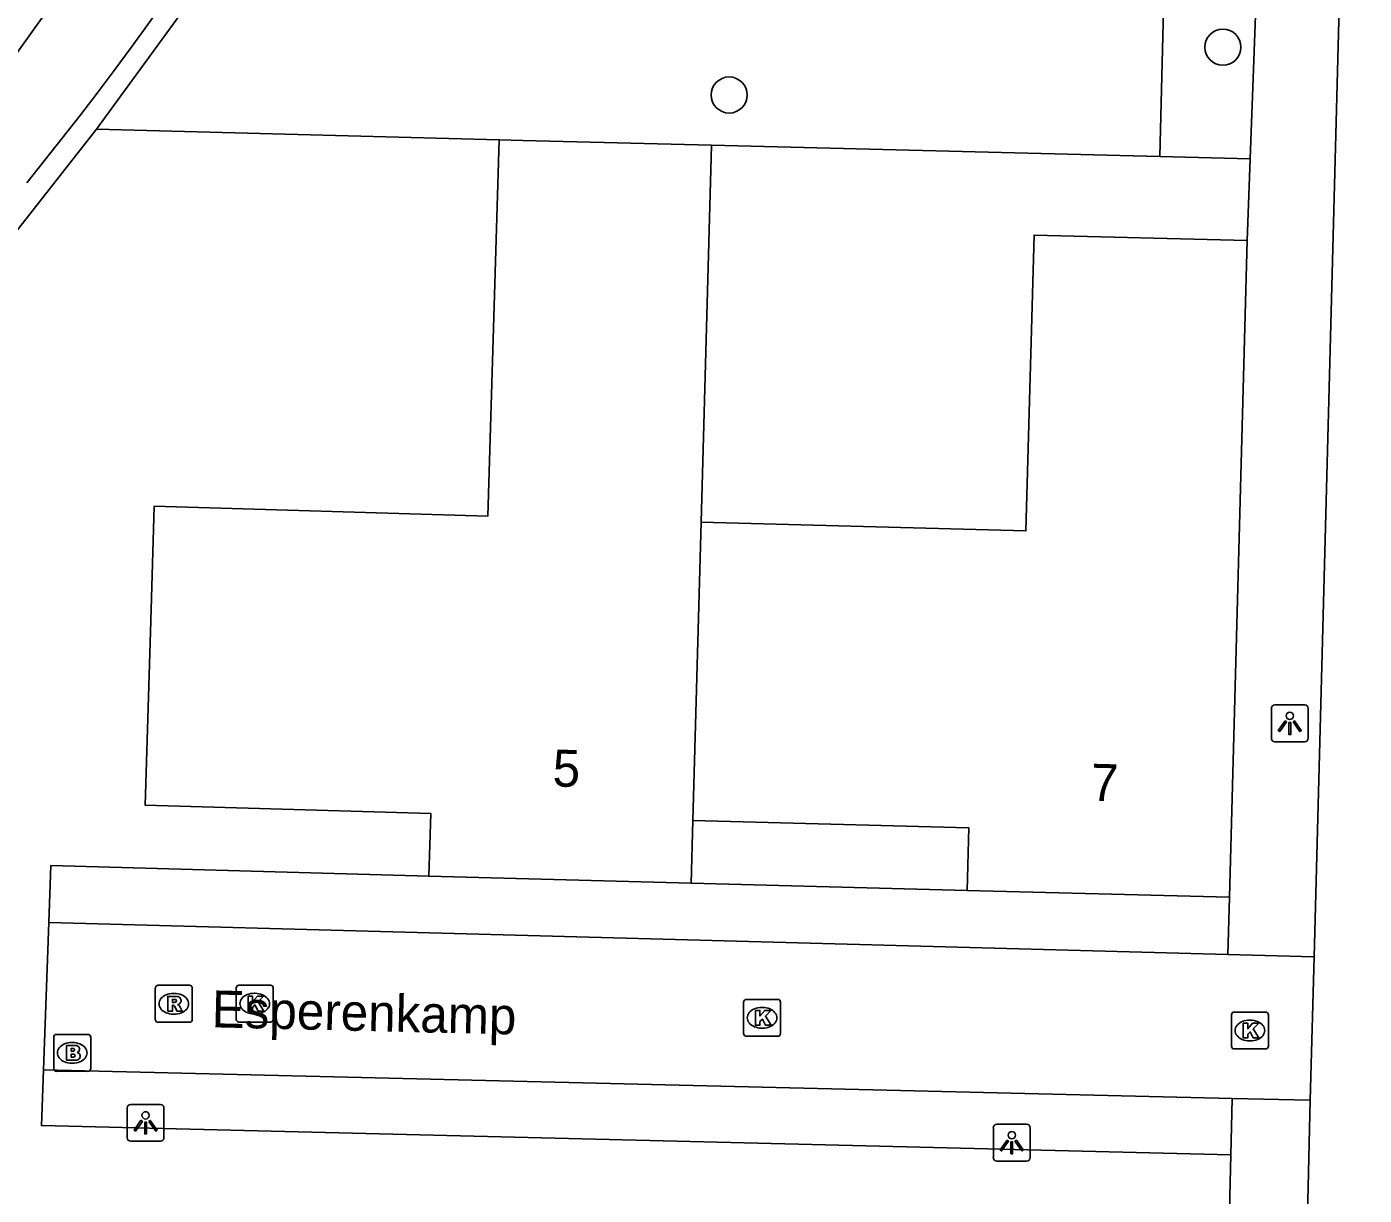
# Model space of a CAD drawing. Extents: x 162082 to 163393, y 388091 to 388632.
# Drawn here: x 162233.21 to 162269.43, y 388303.46 to 388335.1 of the extents above; entities that cross this region are included whole.
import ezdxf

# ---------------------------------------------------------------- set-up
doc = ezdxf.new("R2010")
doc.units = 0
for name, color, linetype in [('IMGEO_Boom', 7, 'Continuous'), ('IMGEO_Brandkraan', 7, 'Continuous'), ('IMGEO_Fietspad_gesloten', 7, 'Continuous'), ('IMGEO_Groenvoorziening', 7, 'Continuous'), ('IMGEO_Kolk', 7, 'Continuous'), ('IMGEO_Lichtpunt', 7, 'Continuous'), ('IMGEO_Muur', 7, 'Continuous'), ('IMGEO_Openbare_ruimte_label', 7, 'Continuous'), ('IMGEO_Pand', 7, 'Continuous'), ('IMGEO_Pand_nummerreeks', 7, 'Continuous'), ('IMGEO_Rijbaan_lokaal_open', 7, 'Continuous'), ('IMGEO_Rioolput', 7, 'Continuous'), ('IMGEO_Voetpad_open', 7, 'Continuous')]:
    doc.layers.add(name, color=color, linetype=linetype)

msp = doc.modelspace()

# ---------------------------------------------------------------- linework, layer by layer
at = {"layer": 'IMGEO_Boom'}
for centre in [(162265.604, 388334.549), (162252.23, 388333.255)]:
    msp.add_circle(centre, 0.489, dxfattribs=at)
at = {"layer": 'IMGEO_Brandkraan'}
for p, q in [((162234.015, 388307.815), (162234.867, 388307.815)), ((162233.94, 388306.889), (162233.94, 388307.741)), ((162234.428, 388307.595), (162234.453, 388307.595)), ((162234.941, 388307.741), (162234.941, 388306.889)), ((162234.867, 388306.815), (162234.015, 388306.815)), ((162234.451, 388307.035), (162234.426, 388307.035))]:
    msp.add_line(p, q, dxfattribs=at)
for points in [[(162234.015, 388307.815), (162234.867, 388307.815)], [(162233.94, 388306.889), (162233.94, 388307.741)], [(162234.288, 388307.515), (162234.288, 388307.115), (162234.501, 388307.115)], [(162234.519, 388307.515), (162234.288, 388307.515)], [(162234.941, 388307.741), (162234.941, 388306.889)], [(162234.467, 388307.434), (162234.413, 388307.434), (162234.413, 388307.358)], [(162234.413, 388307.358), (162234.466, 388307.358)], [(162234.475, 388307.282), (162234.413, 388307.282), (162234.413, 388307.201)], [(162234.413, 388307.201), (162234.475, 388307.201)], [(162234.867, 388306.815), (162234.015, 388306.815)]]:
    msp.add_lwpolyline(points, dxfattribs=at)
for centre, radius, start, end in [((162234.017, 388307.739), 0.0765, 91.552, 178.448), ((162234.017, 388307.739), 0.0765, 91.552, 178.448), ((162234.865, 388307.739), 0.0765, 1.552, 88.448), ((162234.865, 388307.739), 0.0765, 1.552, 88.448), ((162234.523, 388307.37), 0.145, 59.4692, 91.5367), ((162234.548, 388307.417), 0.0922, 285.5137, 58.1501), ((162234.468, 388307.396), 0.0379, 267.8285, 90.9355), ((162234.476, 388307.241), 0.0404, 269.8759, 90.5077), ((162234.507, 388307.366), 0.251, 268.6676, 293.5347), ((162234.553, 388307.225), 0.105, 301.3115, 78.989), ((162234.017, 388306.891), 0.0765, 181.552, 268.448), ((162234.017, 388306.891), 0.0765, 181.552, 268.448), ((162234.865, 388306.891), 0.0765, 271.552, 358.448), ((162234.865, 388306.891), 0.0765, 271.552, 358.448)]:
    msp.add_arc(centre, radius, start, end, dxfattribs=at)
for centre, major_axis, ratio, start_param, end_param in [((162234.427, 388307.315), (-0.387, 0.002), 0.722429, 4.712389, 7.853982), ((162234.452, 388307.315), (-0.39, 0.002), 0.717154, 1.570796, 4.712389)]:
    msp.add_ellipse(centre, major_axis=major_axis, ratio=ratio, start_param=start_param, end_param=end_param, dxfattribs=at)
at = {"layer": 'IMGEO_Fietspad_gesloten'}
msp.add_lwpolyline([(162231.513, 388332.41), (162235.411, 388337.857), (162240.451, 388345.768), (162241.498, 388347.847)], dxfattribs=at)
at = {"layer": 'IMGEO_Groenvoorziening'}
for points in [[(162263.899, 388331.585), (162264.185, 388343.163)], [(162246, 388332.04), (162235.098, 388332.325)], [(162251.75, 388331.897), (162263.899, 388331.585)], [(162263.899, 388331.585), (162266.342, 388331.522)]]:
    msp.add_lwpolyline(points, dxfattribs=at)
at = {"layer": 'IMGEO_Kolk'}
for p, q in [((162238.882, 388308.222), (162238.882, 388309.074)), ((162238.957, 388309.148), (162239.809, 388309.148)), ((162239.37, 388308.928), (162239.395, 388308.928)), ((162239.883, 388309.074), (162239.883, 388308.222)), ((162252.622, 388307.838), (162252.622, 388308.69)), ((162252.697, 388308.764), (162253.549, 388308.764)), ((162253.11, 388308.544), (162253.135, 388308.544)), ((162253.623, 388308.69), (162253.623, 388307.838)), ((162239.393, 388308.368), (162239.368, 388308.368)), ((162265.834, 388307.494), (162265.834, 388308.346)), ((162265.909, 388308.42), (162266.761, 388308.42)), ((162266.322, 388308.2), (162266.347, 388308.2)), ((162266.835, 388308.346), (162266.835, 388307.494)), ((162239.809, 388308.148), (162238.957, 388308.148)), ((162253.133, 388307.984), (162253.108, 388307.984)), ((162253.549, 388307.764), (162252.697, 388307.764)), ((162266.345, 388307.64), (162266.32, 388307.64)), ((162266.761, 388307.42), (162265.909, 388307.42))]:
    msp.add_line(p, q, dxfattribs=at)
for points in [[(162238.882, 388308.222), (162238.882, 388309.074)], [(162238.957, 388309.148), (162239.809, 388309.148)], [(162239.883, 388309.074), (162239.883, 388308.222)], [(162239.203, 388308.848), (162239.326, 388308.848), (162239.326, 388308.697), (162239.456, 388308.848), (162239.62, 388308.848), (162239.474, 388308.697), (162239.627, 388308.448), (162239.475, 388308.448), (162239.39, 388308.612), (162239.326, 388308.545), (162239.326, 388308.448), (162239.203, 388308.448), (162239.203, 388308.848)], [(162252.622, 388307.838), (162252.622, 388308.69)], [(162252.697, 388308.764), (162253.549, 388308.764)], [(162253.623, 388308.69), (162253.623, 388307.838)], [(162252.943, 388308.464), (162253.066, 388308.464), (162253.066, 388308.313), (162253.196, 388308.464), (162253.36, 388308.464), (162253.214, 388308.313), (162253.367, 388308.064), (162253.215, 388308.064), (162253.13, 388308.228), (162253.066, 388308.161), (162253.066, 388308.064), (162252.943, 388308.064), (162252.943, 388308.464)], [(162265.834, 388307.494), (162265.834, 388308.346)], [(162265.909, 388308.42), (162266.761, 388308.42)], [(162266.835, 388308.346), (162266.835, 388307.494)], [(162239.809, 388308.148), (162238.957, 388308.148)], [(162266.155, 388308.12), (162266.278, 388308.12), (162266.278, 388307.969), (162266.408, 388308.12), (162266.572, 388308.12), (162266.426, 388307.969), (162266.579, 388307.72), (162266.427, 388307.72), (162266.342, 388307.884), (162266.278, 388307.817), (162266.278, 388307.72), (162266.155, 388307.72), (162266.155, 388308.12)], [(162253.549, 388307.764), (162252.697, 388307.764)], [(162266.761, 388307.42), (162265.909, 388307.42)]]:
    msp.add_lwpolyline(points, dxfattribs=at)
for centre, start, end in [((162238.959, 388309.072), 91.552, 178.448), ((162238.959, 388309.072), 91.552, 178.448), ((162239.807, 388309.072), 1.552, 88.448), ((162239.807, 388309.072), 1.552, 88.448), ((162252.699, 388308.688), 91.552, 178.448), ((162252.699, 388308.688), 91.552, 178.448), ((162253.547, 388308.688), 1.552, 88.448), ((162253.547, 388308.688), 1.552, 88.448), ((162238.959, 388308.224), 181.552, 268.448), ((162238.959, 388308.224), 181.552, 268.448), ((162239.807, 388308.224), 271.552, 358.448), ((162239.807, 388308.224), 271.552, 358.448), ((162265.911, 388308.344), 91.552, 178.448), ((162265.911, 388308.344), 91.552, 178.448), ((162266.759, 388308.344), 1.552, 88.448), ((162266.759, 388308.344), 1.552, 88.448), ((162252.699, 388307.84), 181.552, 268.448), ((162252.699, 388307.84), 181.552, 268.448), ((162253.547, 388307.84), 271.552, 358.448), ((162253.547, 388307.84), 271.552, 358.448), ((162265.911, 388307.496), 181.552, 268.448), ((162265.911, 388307.496), 181.552, 268.448), ((162266.759, 388307.496), 271.552, 358.448), ((162266.759, 388307.496), 271.552, 358.448)]:
    msp.add_arc(centre, 0.0765, start, end, dxfattribs=at)
for centre, major_axis, ratio, start_param, end_param in [((162239.369, 388308.648), (-0.387, 0.002), 0.722429, 4.712389, 7.853982), ((162239.394, 388308.648), (-0.39, 0.002), 0.717154, 1.570796, 4.712389), ((162253.109, 388308.264), (-0.387, 0.002), 0.722429, 4.712389, 7.853982), ((162253.134, 388308.264), (-0.39, 0.002), 0.717154, 1.570796, 4.712389), ((162266.321, 388307.92), (-0.387, 0.002), 0.722429, 4.712389, 7.853982), ((162266.346, 388307.92), (-0.39, 0.002), 0.717154, 1.570796, 4.712389)]:
    msp.add_ellipse(centre, major_axis=major_axis, ratio=ratio, start_param=start_param, end_param=end_param, dxfattribs=at)
at = {"layer": 'IMGEO_Lichtpunt'}
for p, q in [((162266.916, 388316.642), (162266.916, 388315.835)), ((162266.916, 388316.642), (162266.916, 388315.835)), ((162267.818, 388316.737), (162267.01, 388316.737)), ((162267.818, 388316.737), (162267.01, 388316.737)), ((162267.912, 388315.835), (162267.912, 388316.642)), ((162267.912, 388315.835), (162267.912, 388316.642)), ((162267.01, 388315.741), (162267.818, 388315.741)), ((162267.01, 388315.741), (162267.818, 388315.741)), ((162235.929, 388305.824), (162235.929, 388305.017)), ((162235.929, 388305.824), (162235.929, 388305.017)), ((162236.831, 388305.919), (162236.023, 388305.919)), ((162236.831, 388305.919), (162236.023, 388305.919)), ((162236.925, 388305.017), (162236.925, 388305.824)), ((162236.925, 388305.017), (162236.925, 388305.824)), ((162259.386, 388305.287), (162259.386, 388304.48)), ((162259.386, 388305.287), (162259.386, 388304.48)), ((162260.288, 388305.382), (162259.48, 388305.382)), ((162260.288, 388305.382), (162259.48, 388305.382)), ((162260.382, 388304.48), (162260.382, 388305.287)), ((162260.382, 388304.48), (162260.382, 388305.287)), ((162236.023, 388304.923), (162236.831, 388304.923)), ((162236.023, 388304.923), (162236.831, 388304.923)), ((162259.48, 388304.386), (162260.288, 388304.386)), ((162259.48, 388304.386), (162260.288, 388304.386))]:
    msp.add_line(p, q, dxfattribs=at)
for points in [[(162267.29, 388316.306), (162267.329, 388316.278), (162267.141, 388316.016), (162267.103, 388316.043), (162267.29, 388316.306)], [(162267.392, 388316.258), (162267.439, 388316.258), (162267.439, 388315.936), (162267.392, 388315.936), (162267.392, 388316.258)], [(162267.502, 388316.278), (162267.54, 388316.305), (162267.727, 388316.043), (162267.688, 388316.015), (162267.502, 388316.278)], [(162236.303, 388305.488), (162236.342, 388305.46), (162236.154, 388305.198), (162236.116, 388305.225), (162236.303, 388305.488)], [(162236.405, 388305.44), (162236.452, 388305.44), (162236.452, 388305.118), (162236.405, 388305.118), (162236.405, 388305.44)], [(162236.515, 388305.46), (162236.553, 388305.487), (162236.74, 388305.225), (162236.701, 388305.197), (162236.515, 388305.46)], [(162259.76, 388304.951), (162259.799, 388304.923), (162259.611, 388304.661), (162259.573, 388304.688), (162259.76, 388304.951)], [(162259.972, 388304.923), (162260.01, 388304.95), (162260.197, 388304.688), (162260.158, 388304.66), (162259.972, 388304.923)], [(162259.862, 388304.903), (162259.909, 388304.903), (162259.909, 388304.581), (162259.862, 388304.581), (162259.862, 388304.903)]]:
    msp.add_lwpolyline(points, dxfattribs=at)
for centre in [(162267.415, 388316.44), (162236.428, 388305.622), (162259.885, 388305.085)]:
    msp.add_circle(centre, 0.0994, dxfattribs=at)
for centre, start, end in [((162267.01, 388316.642), 90, 180), ((162267.01, 388316.642), 90, 180), ((162267.818, 388316.642), 0, 90), ((162267.818, 388316.642), 0, 90), ((162267.01, 388315.835), 180, 270), ((162267.01, 388315.835), 180, 270), ((162267.818, 388315.835), 270, 0), ((162267.818, 388315.835), 270, 360), ((162236.023, 388305.824), 90, 180), ((162236.023, 388305.824), 90, 180), ((162236.831, 388305.824), 0, 90), ((162236.831, 388305.824), 0, 90), ((162259.48, 388305.287), 90, 180), ((162259.48, 388305.287), 90, 180), ((162260.288, 388305.287), 0, 90), ((162260.288, 388305.287), 0, 90), ((162236.023, 388305.017), 180, 270), ((162236.023, 388305.017), 180, 270), ((162236.831, 388305.017), 270, 0), ((162236.831, 388305.017), 270, 360), ((162259.48, 388304.48), 180, 270), ((162259.48, 388304.48), 180, 270), ((162260.288, 388304.48), 270, 0), ((162260.288, 388304.48), 270, 360)]:
    msp.add_arc(centre, 0.0946, start, end, dxfattribs=at)
at = {"layer": 'IMGEO_Muur'}
for points in [[(162235.098, 388332.325), (162238.245, 388336.654), (162241.627, 388341.988), (162243.888, 388346.035)], [(162235.098, 388332.325), (162227.2, 388322.27)]]:
    msp.add_lwpolyline(points, dxfattribs=at)
msp.add_arc((162161.675, 388388.966), 92.147, 320.92318, 351.45801, dxfattribs=at)
at = {"layer": 'IMGEO_Pand'}
for points in [[(162244.1, 388312.1), (162244.15, 388313.8), (162236.42, 388314.02), (162236.568, 388319.018), (162236.66, 388322.12), (162245.7, 388321.85), (162246, 388332.04)], [(162251.75, 388331.897), (162246.642, 388332.024), (162246, 388332.04)], [(162251.47, 388321.69), (162251.75, 388331.897)], [(162266.26, 388329.31), (162260.49, 388329.46), (162260.27, 388321.45), (162251.47, 388321.69)], [(162265.78, 388311.53), (162266.26, 388329.31)], [(162251.47, 388321.69), (162251.25, 388313.61)], [(162251.2, 388311.91), (162251.25, 388313.61)], [(162251.25, 388313.61), (162258.72, 388313.41), (162258.68, 388311.71)], [(162244.1, 388312.1), (162251.2, 388311.91)], [(162258.68, 388311.71), (162265.78, 388311.53)]]:
    msp.add_lwpolyline(points, dxfattribs=at)
at = {"layer": 'IMGEO_Rijbaan_lokaal_open'}
for points in [[(162267.313, 388361.316), (162269.431, 388361.317), (162268.074, 388309.912)], [(162233.661, 388306.857), (162233.803, 388310.843)], [(162233.803, 388310.843), (162265.741, 388309.975)], [(162265.741, 388309.975), (162268.074, 388309.912)], [(162268.074, 388309.912), (162267.97, 388306.031)], [(162265.854, 388306.082), (162233.661, 388306.857)], [(162267.97, 388306.031), (162265.854, 388306.082)], [(162267.474, 388284.544), (162267.97, 388306.031)]]:
    msp.add_lwpolyline(points, dxfattribs=at)
at = {"layer": 'IMGEO_Rioolput'}
for p, q in [((162236.691, 388308.218), (162236.691, 388309.07)), ((162236.766, 388309.144), (162237.618, 388309.144)), ((162237.179, 388308.924), (162237.204, 388308.924)), ((162237.692, 388309.07), (162237.692, 388308.218)), ((162237.202, 388308.364), (162237.177, 388308.364)), ((162237.618, 388308.144), (162236.766, 388308.144))]:
    msp.add_line(p, q, dxfattribs=at)
for points in [[(162236.691, 388308.218), (162236.691, 388309.07)], [(162236.766, 388309.144), (162237.618, 388309.144)], [(162237.692, 388309.07), (162237.692, 388308.218)], [(162237.28, 388308.842), (162237.028, 388308.844), (162237.028, 388308.444)], [(162237.028, 388308.444), (162237.152, 388308.444), (162237.152, 388308.606), (162237.163, 388308.606)], [(162237.206, 388308.763), (162237.152, 388308.763), (162237.152, 388308.682)], [(162237.152, 388308.682), (162237.204, 388308.682)], [(162237.21, 388308.577), (162237.281, 388308.444), (162237.421, 388308.444), (162237.356, 388308.57)], [(162237.618, 388308.144), (162236.766, 388308.144)]]:
    msp.add_lwpolyline(points, dxfattribs=at)
for centre, radius, start, end in [((162236.768, 388309.068), 0.0765, 91.552, 178.448), ((162236.768, 388309.068), 0.0765, 91.552, 178.448), ((162237.616, 388309.068), 0.0765, 1.552, 88.448), ((162237.616, 388309.068), 0.0765, 1.552, 88.448), ((162237.162, 388308.553), 0.0533, 26.0293, 88.6989), ((162237.188, 388308.871), 0.19, 274.7715, 282.9687), ((162237.212, 388308.667), 0.0964, 77.0061, 93.1865), ((162237.226, 388308.724), 0.0378, 276.6634, 79.6772), ((162237.279, 388308.732), 0.109, 350.3612, 89.416), ((162237.277, 388308.732), 0.112, 277.5842, 350.9817), ((162237.261, 388308.517), 0.108, 29.5134, 73.7905), ((162236.768, 388308.22), 0.0765, 181.552, 268.448), ((162236.768, 388308.22), 0.0765, 181.552, 268.448), ((162237.616, 388308.22), 0.0765, 271.552, 358.448), ((162237.616, 388308.22), 0.0765, 271.552, 358.448)]:
    msp.add_arc(centre, radius, start, end, dxfattribs=at)
for centre, major_axis, ratio, start_param, end_param in [((162237.178, 388308.644), (-0.387, 0.002), 0.722429, 4.712389, 7.853982), ((162237.203, 388308.644), (-0.39, 0.002), 0.717154, 1.570796, 4.712389)]:
    msp.add_ellipse(centre, major_axis=major_axis, ratio=ratio, start_param=start_param, end_param=end_param, dxfattribs=at)
at = {"layer": 'IMGEO_Voetpad_open'}
for points in [[(162267.163, 388353.633), (162267.11, 388352.168), (162266.342, 388331.522)], [(162266.342, 388331.522), (162266.26, 388329.31)], [(162233.803, 388310.843), (162233.858, 388312.388), (162244.1, 388312.1)], [(162258.68, 388311.71), (162251.2, 388311.91)], [(162265.741, 388309.975), (162265.78, 388311.53)], [(162265.816, 388304.552), (162233.607, 388305.344), (162233.661, 388306.857)], [(162265.854, 388306.082), (162265.816, 388304.552)], [(162265.816, 388304.552), (162265.335, 388284.581)]]:
    msp.add_lwpolyline(points, dxfattribs=at)

# ---------------------------------------------------------------- texts
at = {"layer": 'IMGEO_Openbare_ruimte_label'}
msp.add_text('Esperenkamp', height=1, rotation=358.6252, dxfattribs=at).set_placement((162238.21, 388308.008))
at = {"layer": 'IMGEO_Pand_nummerreeks'}
for s, rotation, p in [('5', 358.4671, (162247.442, 388314.532)), ('7', 358.5477, (162262.018, 388314.146))]:
    msp.add_text(s, height=1, rotation=rotation, dxfattribs=at).set_placement(p)

doc.saveas('drawing.dxf')
